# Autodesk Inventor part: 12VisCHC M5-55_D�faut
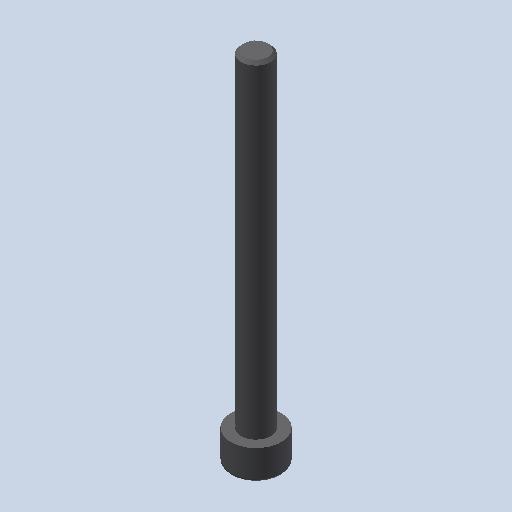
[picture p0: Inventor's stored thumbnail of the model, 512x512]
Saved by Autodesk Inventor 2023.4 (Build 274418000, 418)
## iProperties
Created: 2011-01
Part Number: 12VisCHC M5-55_D�faut
Document SubType Name: Modeling
Designer: eric
Density: 1 g/cm^3
Mass: 1.32578 g
Surface Area: 11.3482 cm^2
Volume: 1.32578 cm^3
Material: Générique
Appearance: Red
Author: eric
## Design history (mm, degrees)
feature "Base1"
node "Corps solides"
node "Corps surfaciques"
node "Solide1"
